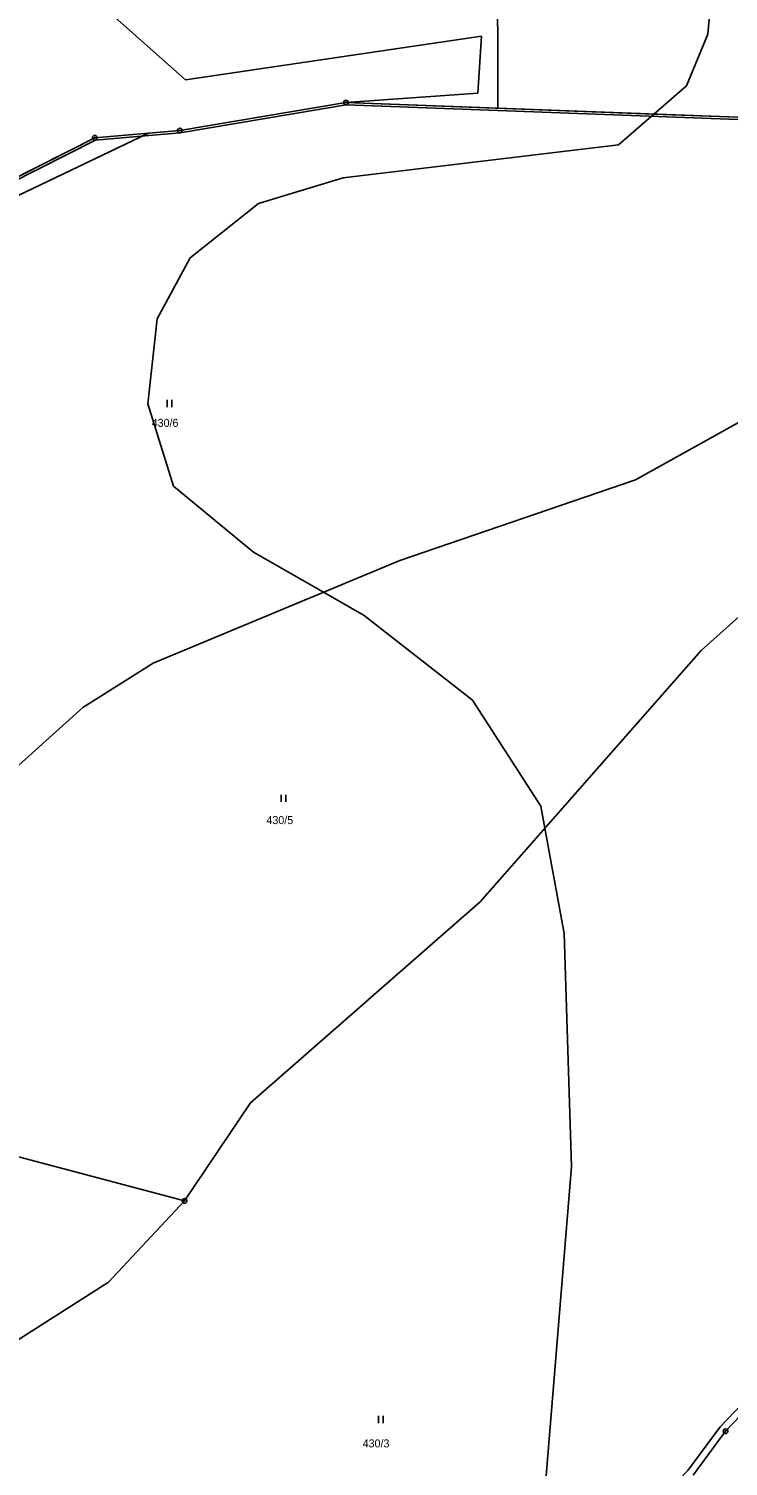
# Model space of a CAD drawing. Extents: x -547623 to -538651, y -1096714 to -1086522.
# Drawn here: x -543577.8 to -543429.2, y -1093716.2 to -1093410.9 of the extents above; entities that cross this region are included whole.
import ezdxf

# ---------------------------------------------------------------- set-up
doc = ezdxf.new("R2010")
doc.units = 0
for name, color, linetype in [('Vrstva 1', 7, 'Continuous'), ('Vrstva 25', 7, 'Continuous'), ('Vrstva 41', 7, 'Continuous'), ('Vrstva 52', 7, 'Continuous'), ('Vrstva 62', 7, 'Continuous'), ('Vrstva 83', 7, 'Continuous'), ('Vrstva 86', 7, 'Continuous')]:
    doc.layers.add(name, color=color, linetype=linetype)

msp = doc.modelspace()

# ---------------------------------------------------------------- linework, layer by layer
at = {"layer": 'Vrstva 1'}
for points in [[(-543478.11, -1093411.56), (-543478.57, -1093396.27)], [(-543544.47, -1093421.73), (-543567.54, -1093401.21)], [(-543478.13, -1093427.75), (-543478.11, -1093411.56)], [(-543481.56, -1093412.43), (-543544.47, -1093421.73)], [(-543482.39, -1093424.56), (-543481.56, -1093412.43)], [(-543510.38, -1093426.55), (-543482.39, -1093424.56)], [(-543603.17, -1093457.35), (-543552.35, -1093433.05)], [(-543423.66, -1093492.62), (-543448.89, -1093506.69)], [(-543390.02, -1093502.75), (-543434.9, -1093542.89)], [(-543448.89, -1093506.69), (-543498.97, -1093523.77)], [(-543498.97, -1093523.77), (-543551.37, -1093545.64)], [(-543434.9, -1093542.89), (-543481.89, -1093596.29)], [(-543551.37, -1093545.64), (-543566.29, -1093555.01)], [(-543566.29, -1093555.01), (-543584.26, -1093571.17)], [(-543481.89, -1093596.29), (-543530.7, -1093639.01)], [(-543544.66, -1093659.82), (-543662.51, -1093628.6)], [(-543530.7, -1093639.01), (-543544.66, -1093659.82)], [(-543544.66, -1093659.82), (-543560.82, -1093677.11)], [(-543390.79, -1093668.11), (-543429.74, -1093708.75)], [(-543560.82, -1093677.11), (-543592.96, -1093697.52)], [(-543429.74, -1093708.75), (-543436.63, -1093718.08)]]:
    msp.add_lwpolyline(points, dxfattribs=at)
at = {"layer": 'Vrstva 25'}
for p, q in [((-543548.35, -1093491.21), (-543548.35, -1093489.71)), ((-543547.35, -1093491.21), (-543547.35, -1093489.71)), ((-543524.16, -1093575.06), (-543524.16, -1093573.56)), ((-543523.16, -1093575.06), (-543523.16, -1093573.56)), ((-543503.48, -1093707), (-543503.48, -1093705.5)), ((-543502.48, -1093707), (-543502.48, -1093705.5))]:
    msp.add_line(p, q, dxfattribs=at)
at = {"layer": 'Vrstva 41'}
for p, q in [((-543510.38, -1093426.55), (-543545.7, -1093432.49)), ((-543510.38, -1093426.55), (-543545.7, -1093432.49)), ((-543478.13, -1093427.75), (-543510.38, -1093426.55)), ((-543478.13, -1093427.75), (-543510.38, -1093426.55)), ((-543427.1, -1093429.66), (-543478.13, -1093427.75)), ((-543427.1, -1093429.66), (-543478.13, -1093427.75)), ((-543563.75, -1093434.01), (-543606.35, -1093455.57)), ((-543563.75, -1093434.01), (-543606.35, -1093455.57))]:
    msp.add_line(p, q, dxfattribs=at)
for points in [[(-543552.35, -1093433.05), (-543563.75, -1093434.01)], [(-543552.35, -1093433.05), (-543563.75, -1093434.01)], [(-543545.7, -1093432.49), (-543552.35, -1093433.05)], [(-543545.7, -1093432.49), (-543552.35, -1093433.05)]]:
    msp.add_lwpolyline(points, dxfattribs=at)
at = {"layer": 'Vrstva 52'}
for points in [[(-543232.87, -1093288.14), (-543247.82, -1093315.94), (-543263.86, -1093344.05), (-543276.83, -1093367.83), (-543283.08, -1093385.25), (-543290.89, -1093405.97), (-543300.68, -1093432.82), (-543316.5, -1093480.2), (-543320.77, -1093479.17), (-543322.02, -1093478.87), (-543326.47, -1093477.79), (-543340.87, -1093469.3), (-543350.24, -1093459.78), (-543367.08, -1093442.21), (-543383.96, -1093434.44), (-543399.63, -1093430.39), (-543427.1, -1093429.66), (-543444.95, -1093428.99)], [(-543444.95, -1093428.99), (-543438, -1093423), (-543433.5, -1093412), (-543431.5, -1093389.5)], [(-543668.62, -1093490.9), (-543660.76, -1093484.95), (-543655.28, -1093481.97), (-543617.21, -1093461.25), (-543606.35, -1093455.57), (-543563.75, -1093434.01), (-543552.35, -1093433.05), (-543545.7, -1093432.49), (-543510.38, -1093426.55), (-543444.95, -1093428.99)], [(-543444.95, -1093428.99), (-543478.13, -1093427.75), (-543510.38, -1093426.55), (-543545.7, -1093432.49), (-543552.35, -1093433.05), (-543563.75, -1093434.01), (-543606.35, -1093455.57), (-543617.21, -1093461.25), (-543655.28, -1093481.97), (-543660.76, -1093484.95), (-543668.62, -1093490.9)], [(-543464, -1093603), (-543468.14, -1093580.66), (-543469, -1093576), (-543483.5, -1093553.5), (-543506.5, -1093535.5), (-543515.16, -1093530.53), (-543530, -1093522), (-543547, -1093508), (-543552.5, -1093490.5), (-543550.5, -1093472.5), (-543543.5, -1093459.5), (-543529, -1093448), (-543511, -1093442.5), (-543452.5, -1093435.5), (-543444.95, -1093428.99)], [(-543444.95, -1093428.99), (-543427.1, -1093429.66), (-543399.63, -1093430.39), (-543383.96, -1093434.44), (-543367.08, -1093442.21), (-543350.24, -1093459.78), (-543340.87, -1093469.3), (-543326.47, -1093477.79), (-543320.77, -1093479.17), (-543316.5, -1093480.2), (-543309.79, -1093483.07), (-543273.73, -1093498.03), (-543222.69, -1093506.2), (-543160.35, -1093512.71), (-543131.57, -1093519.72), (-543116.15, -1093525.3), (-543085.83, -1093536.57)], [(-543763.21, -1093707.8), (-543750, -1093716.29), (-543738, -1093724), (-543678, -1093742.5), (-543662.28, -1093744.7), (-543658.26, -1093745.26), (-543654, -1093745.86), (-543606.5, -1093752.5), (-543565.5, -1093752), (-543509, -1093753.5), (-543479.5, -1093748), (-543473.5, -1093744), (-543469, -1093732), (-543462.5, -1093652.5), (-543464, -1093603)]]:
    msp.add_lwpolyline(points, dxfattribs=at)
at = {"layer": 'Vrstva 62'}
for points in [[(-543545.64, -1093432.99), (-543510.34, -1093427.05)], [(-543510.34, -1093427.05), (-543478.15, -1093428.25)], [(-543478.15, -1093428.25), (-543427.11, -1093430.16), (-543399.7, -1093430.88), (-543384.12, -1093434.91), (-543367.37, -1093442.62), (-543350.59, -1093460.12), (-543341.18, -1093469.69), (-543326.66, -1093478.25), (-543322.42, -1093479.29)], [(-543606.12, -1093456.01), (-543563.61, -1093434.5), (-543552.3, -1093433.54)], [(-543552.3, -1093433.54), (-543545.64, -1093432.99)], [(-543322.42, -1093479.29), (-543323.75, -1093482.74), (-543343.35, -1093533.98), (-543352.69, -1093567.3), (-543368.29, -1093617.27), (-543377.1, -1093646.82), (-543384.11, -1093658.03), (-543391.9, -1093667.1), (-543430.88, -1093707.78), (-543437.77, -1093717.1), (-543493.74, -1093775.05), (-543554.19, -1093841.65), (-543666.67, -1093961.99)]]:
    msp.add_lwpolyline(points, dxfattribs=at)
at = {"layer": 'Vrstva 83'}
for centre, radius in [((-543510.38, -1093426.55), 0.5), ((-543510.38, -1093426.55), 0.5), ((-543510.38, -1093426.55), 0.1), ((-543510.38, -1093426.55), 0.1), ((-543563.75, -1093434.01), 0.5), ((-543563.75, -1093434.01), 0.5), ((-543545.7, -1093432.49), 0.5), ((-543545.7, -1093432.49), 0.5), ((-543545.7, -1093432.49), 0.1), ((-543545.7, -1093432.49), 0.1), ((-543563.75, -1093434.01), 0.1), ((-543563.75, -1093434.01), 0.1), ((-543544.66, -1093659.82), 0.5), ((-543544.66, -1093659.82), 0.1), ((-543429.74, -1093708.75), 0.5), ((-543429.74, -1093708.75), 0.1)]:
    msp.add_circle(centre, radius, dxfattribs=at)

# ---------------------------------------------------------------- texts
at = {"layer": 'Vrstva 86'}
for s, p in [('430/6', (-543551.67, -1093495.42)), ('430/5', (-543527.29, -1093579.79)), ('430/3', (-543506.84, -1093712.18))]:
    msp.add_text(s, height=1.7, dxfattribs=at).set_placement(p)

doc.saveas('drawing.dxf')
